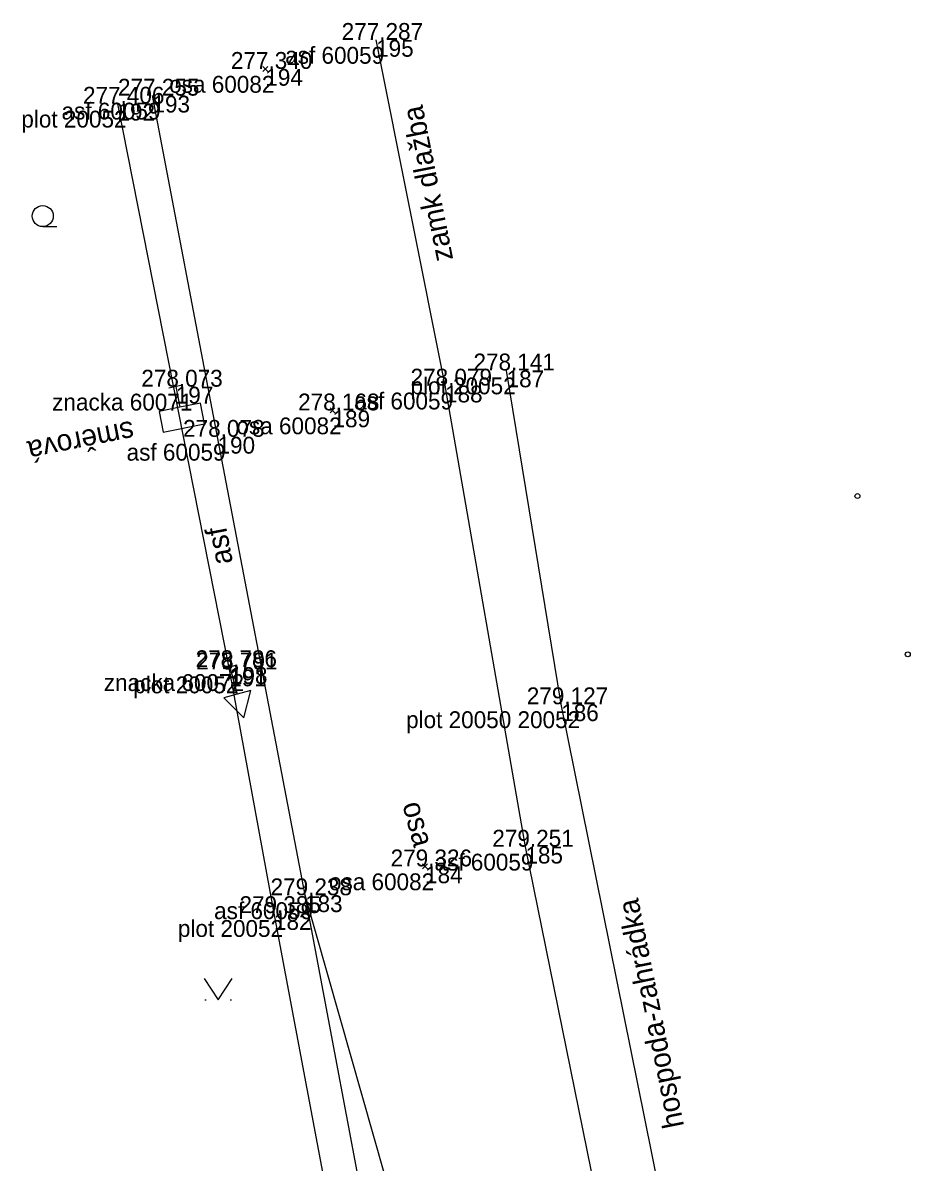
# Model space of a CAD drawing. Extents: x -728659 to -728362, y -1073110 to -1072943.
# Drawn here: x -728528.07 to -728496.45, y -1073004.33 to -1072963.74 of the extents above; entities that cross this region are included whole.
import ezdxf

# ---------------------------------------------------------------- set-up
doc = ezdxf.new("R2010")
doc.units = 0
for name, color, linetype in [('Vrstva 17', 7, 'Continuous'), ('Vrstva 49', 7, 'Continuous'), ('Vrstva 51', 7, 'Continuous'), ('Vrstva 58', 7, 'Continuous'), ('Vrstva 59', 7, 'Continuous'), ('Vrstva 60', 7, 'Continuous'), ('Vrstva 61', 7, 'Continuous'), ('Vrstva 62', 7, 'Continuous'), ('Vrstva 63', 7, 'Continuous')]:
    doc.layers.add(name, color=color, linetype=linetype)

msp = doc.modelspace()

# ---------------------------------------------------------------- linework, layer by layer
at = {"layer": 'Vrstva 17'}
for p, q in [((-728508.888, -1072988.018), (-728510.834, -1072976.125)), ((-728504.103, -1073011.723), (-728508.888, -1072988.018))]:
    msp.add_line(p, q, dxfattribs=at)
msp.add_lwpolyline([(-728524.699, -1072966.621), (-728520.715, -1072986.778), (-728519.122, -1072995.457), (-728515.236, -1073016.2)], dxfattribs=at)
at = {"layer": 'Vrstva 49'}
for p, q in [((-728519.343, -1072965.469), (-728519.519, -1072965.293)), ((-728519.343, -1072965.293), (-728519.519, -1072965.469)), ((-728516.948, -1072977.637), (-728517.124, -1072977.461)), ((-728516.948, -1072977.461), (-728517.124, -1072977.637)), ((-728513.651, -1072993.882), (-728513.827, -1072993.706)), ((-728513.651, -1072993.706), (-728513.827, -1072993.882))]:
    msp.add_line(p, q, dxfattribs=at)
at = {"layer": 'Vrstva 51'}
for p, q in [((-728522.377, -1072976.654), (-728522.867, -1072976.752)), ((-728520.45, -1072986.63), (-728520.932, -1072986.762))]:
    msp.add_line(p, q, dxfattribs=at)
for points in [[(-728507.377, -1073006.769), (-728510.163, -1072993.092), (-728513.027, -1072976.664), (-728515.483, -1072964.348)], [(-728515.484, -1073008.258), (-728518.016, -1072994.823), (-728521.133, -1072978.489), (-728523.451, -1072966.335)], [(-728522.622, -1072976.703), (-728522.476, -1072977.439), (-728523.212, -1072977.585), (-728523.066, -1072978.32), (-728521.594, -1072978.028), (-728521.74, -1072977.293), (-728522.476, -1072977.439)], [(-728520.691, -1072986.696), (-728520.428, -1072987.661), (-728520.91, -1072987.792), (-728520.198, -1072988.505), (-728519.945, -1072987.529), (-728520.428, -1072987.661)], [(-728512.398, -1073021.312), (-728513.144, -1073011.93), (-728518.016, -1072994.823)]]:
    msp.add_lwpolyline(points, dxfattribs=at)
at = {"layer": 'Vrstva 58'}
for p, q in [((-728527.361, -1072971.001), (-728526.861, -1072971.001)), ((-728521.585, -1072998.544), (-728521.535, -1072998.544)), ((-728520.685, -1072998.544), (-728520.635, -1072998.544))]:
    msp.add_line(p, q, dxfattribs=at)
msp.add_lwpolyline([(-728521.61, -1072997.794), (-728521.11, -1072998.544), (-728520.61, -1072997.794)], dxfattribs=at)
msp.add_circle((-728527.361, -1072970.626), 0.375, dxfattribs=at)
at = {"layer": 'Vrstva 59'}
for centre in [(-728498.334, -1072980.601), (-728496.54, -1072986.24)]:
    msp.add_circle(centre, 0.0873, dxfattribs=at)
at = {"layer": 'Vrstva 60'}
for p, q in [((-728515.483, -1072964.348), (-728515.483, -1072964.348)), ((-728519.431, -1072965.381), (-728519.431, -1072965.381)), ((-728523.451, -1072966.335), (-728523.451, -1072966.335)), ((-728524.699, -1072966.621), (-728524.699, -1072966.621)), ((-728510.834, -1072976.125), (-728510.834, -1072976.125)), ((-728522.622, -1072976.703), (-728522.622, -1072976.703)), ((-728513.027, -1072976.664), (-728513.027, -1072976.664)), ((-728517.036, -1072977.549), (-728517.036, -1072977.549)), ((-728521.133, -1072978.489), (-728521.133, -1072978.489)), ((-728520.715, -1072986.778), (-728520.715, -1072986.778)), ((-728520.691, -1072986.696), (-728520.691, -1072986.696)), ((-728508.888, -1072988.018), (-728508.888, -1072988.018)), ((-728510.163, -1072993.092), (-728510.163, -1072993.092)), ((-728513.739, -1072993.794), (-728513.739, -1072993.794)), ((-728518.016, -1072994.823), (-728518.016, -1072994.823)), ((-728519.122, -1072995.457), (-728519.122, -1072995.457))]:
    msp.add_line(p, q, dxfattribs=at)

# ---------------------------------------------------------------- texts
at = {"layer": 'Vrstva 51'}
for s, rotation, p in [('zamk dlažba', 101.2777, (-728512.733, -1072972.162)), ('asf', 100.8038, (-728520.582, -1072982.971))]:
    msp.add_text(s, height=0.75, rotation=rotation, dxfattribs=at).set_placement(p)
at = {"layer": 'Vrstva 60'}
for s, p in [('195', (-728515.483, -1072964.948)), ('194', (-728519.431, -1072965.981)), ('193', (-728523.451, -1072966.935)), ('192', (-728524.699, -1072967.221)), ('187', (-728510.834, -1072976.725)), ('197', (-728522.622, -1072977.303)), ('188', (-728513.027, -1072977.264)), ('189', (-728517.036, -1072978.149)), ('190', (-728521.133, -1072979.089)), ('191', (-728520.715, -1072987.378)), ('198', (-728520.691, -1072987.296)), ('186', (-728508.888, -1072988.618)), ('185', (-728510.163, -1072993.692)), ('184', (-728513.739, -1072994.394)), ('183', (-728518.016, -1072995.423)), ('182', (-728519.122, -1072996.057))]:
    msp.add_text(s, height=0.6, dxfattribs=at).set_placement(p)
at = {"layer": 'Vrstva 61'}
for s, p in [('277.287', (-728516.709, -1072964.348)), ('277.340', (-728520.656, -1072965.381)), ('277.406', (-728525.925, -1072966.621)), ('277.255', (-728524.679, -1072966.335)), ('278.141', (-728512.013, -1072976.125)), ('278.073', (-728523.848, -1072976.703)), ('278.079', (-728514.254, -1072976.664)), ('278.168', (-728518.263, -1072977.549)), ('278.078', (-728522.36, -1072978.489)), ('278.786', (-728521.917, -1072986.696)), ('278.791', (-728521.894, -1072986.778)), ('279.127', (-728510.114, -1072988.018)), ('279.251', (-728511.342, -1072993.092)), ('279.326', (-728514.965, -1072993.794)), ('279.238', (-728519.243, -1072994.823)), ('279.385', (-728520.35, -1072995.457))]:
    msp.add_text(s, height=0.6, dxfattribs=at).set_placement(p)
at = {"layer": 'Vrstva 62'}
for s, p in [('asf 60059', (-728518.722, -1072965.198)), ('osa 60082', (-728522.855, -1072966.231)), ('plot 20052', (-728528.123, -1072967.471)), ('asf 60059', (-728526.69, -1072967.185)), ('plot 20052', (-728514.258, -1072976.975)), ('znacka 60071', (-728527.025, -1072977.553)), ('asf 60059', (-728516.266, -1072977.514)), ('osa 60082', (-728520.46, -1072978.399)), ('asf 60059', (-728524.372, -1072979.339)), ('znacka 60072', (-728525.185, -1072987.546)), ('plot 20052', (-728524.139, -1072987.628)), ('plot 20050 20052', (-728514.415, -1072988.868)), ('asf 60059', (-728513.402, -1072993.942)), ('osa 60082', (-728517.163, -1072994.644)), ('asf 60059', (-728521.255, -1072995.673)), ('plot 20052', (-728522.546, -1072996.307))]:
    msp.add_text(s, height=0.6, dxfattribs=at).set_placement(p)
at = {"layer": 'Vrstva 63'}
for s, rotation, p in [('směrová', 191.2197, (-728524.181, -1072977.913)), ('osa', 285.0418, (-728514.551, -1072991.592)), ('hospoda-zahrádka', 101.4122, (-728504.508, -1073003.043))]:
    msp.add_text(s, height=0.75, rotation=rotation, dxfattribs=at).set_placement(p)

doc.saveas('drawing.dxf')
